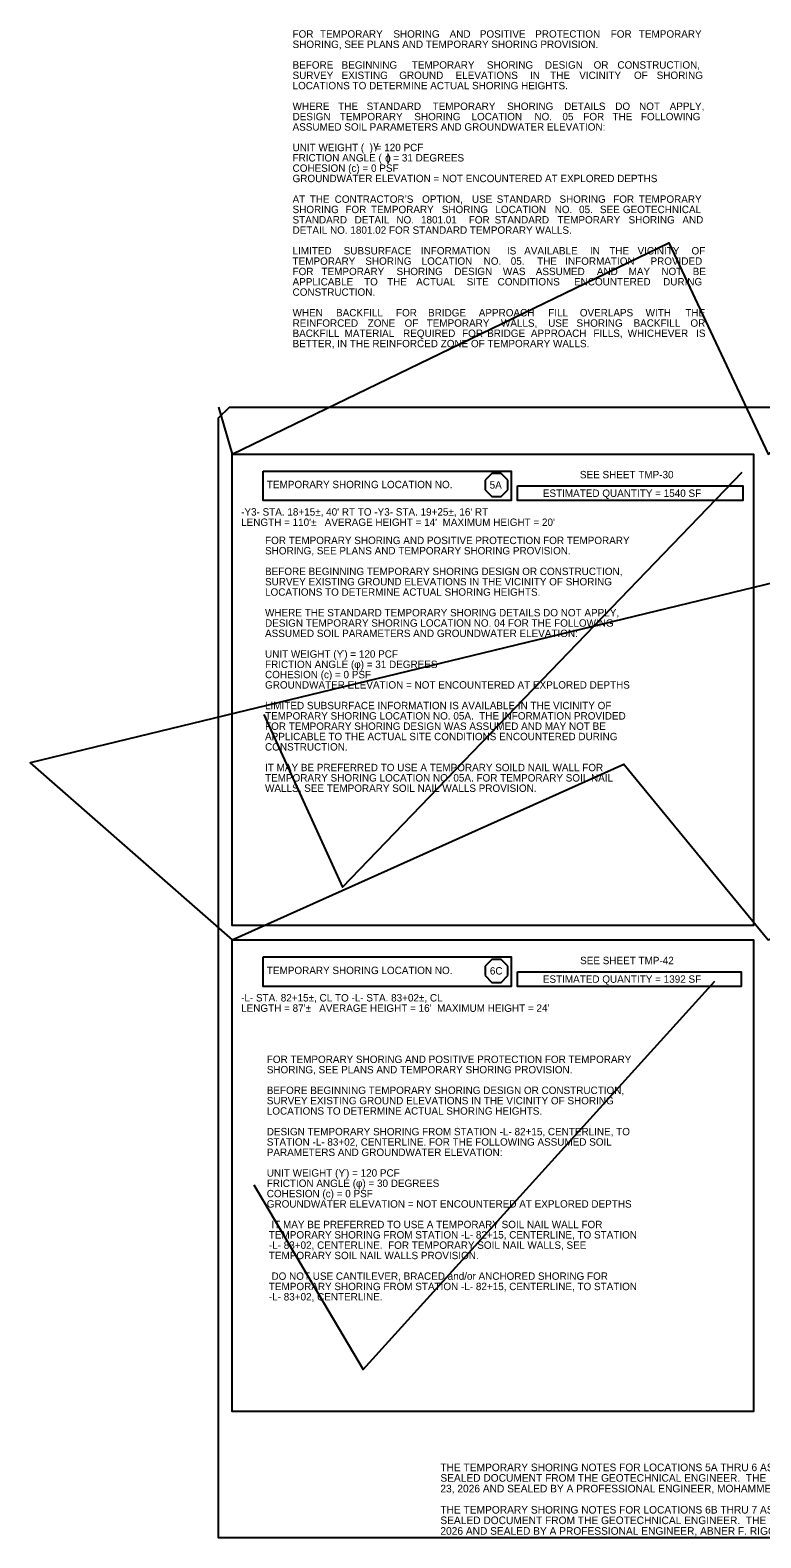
# Model space of a CAD drawing. Extents: x 2487012 to 2497594, y 369516 to 371986.
# Drawn here: x 2492395 to 2493067, y 370242 to 371629 of the extents above; entities that cross this region are included whole.
import ezdxf

# ---------------------------------------------------------------- set-up
doc = ezdxf.new("R2010")
doc.units = 0
for name, color, linetype in [('Scratch_Level_2', 7, 'Continuous'), ('Scratch_Level_3', 7, 'Continuous'), ('Scratch_Level_4', 7, 'Continuous'), ('Scratch_Level_6', 7, 'Continuous'), ('TC LABEL TEMP SHORING', 7, 'Continuous'), ('TC SHEET BORDER LINE THIN', 7, 'Continuous'), ('TC SHEET LAYOUT SHAPE', 7, 'Continuous'), ('TC SHEET TEXT', 7, 'Continuous')]:
    doc.layers.add(name, color=color, linetype=linetype)

msp = doc.modelspace()

# ---------------------------------------------------------------- linework, layer by layer
at = {"layer": 'Scratch_Level_2'}
msp.add_lwpolyline([(2492600.6, 370566.9), (2492701.1, 370397.1), (2493024.5, 370754.4)], dxfattribs=at)
at = {"layer": 'Scratch_Level_3'}
msp.add_line((2492568.3, 371282.3), (2492568.3, 371282.3), dxfattribs=at)
at = {"layer": 'Scratch_Level_4'}
msp.add_lwpolyline([(2492609.8, 370999.5), (2492682.2, 370840.9), (2493049.8, 371222.4)], dxfattribs=at)
at = {"layer": 'Scratch_Level_6'}
msp.add_lwpolyline([(2492568.3, 371282.3), (2492580.7, 371239.1), (2492982.2, 371433.4), (2493073.6, 371239.1), (2493388.3, 371445.4), (2493566.5, 371239.1), (2492395, 370955.2), (2492580.7, 370792.3), (2492940.9, 370953.9), (2493073.6, 370792.3), (2493429.6, 370924.6), (2493566.5, 370792.3)], dxfattribs=at)
at = {"layer": 'TC LABEL TEMP SHORING'}
for p, q in [((2492819.6, 371221.2), (2492813.5, 371215)), ((2492813.5, 371215), (2492813.5, 371206.3)), ((2492828.2, 371221.2), (2492819.6, 371221.2)), ((2492834.3, 371215), (2492828.2, 371221.2)), ((2492834.3, 371206.3), (2492834.3, 371215)), ((2492813.5, 371206.3), (2492819.6, 371200.1)), ((2492828.2, 371200.1), (2492834.3, 371206.3)), ((2492819.6, 371200.1), (2492828.2, 371200.1)), ((2492819.6, 370774.3), (2492813.5, 370768.1)), ((2492828.2, 370774.3), (2492819.6, 370774.3)), ((2492834.3, 370768.1), (2492828.2, 370774.3)), ((2492813.5, 370768.1), (2492813.5, 370759.4)), ((2492813.5, 370759.4), (2492819.6, 370753.2)), ((2492828.2, 370753.2), (2492834.3, 370759.4)), ((2492834.3, 370759.4), (2492834.3, 370768.1)), ((2492819.6, 370753.2), (2492828.2, 370753.2))]:
    msp.add_line(p, q, dxfattribs=at)
at = {"layer": 'TC SHEET BORDER LINE THIN'}
for points in [[(2492580.7, 371239.1), (2493060.1, 371239.1), (2493060.1, 370805.5), (2492580.7, 370805.5)], [(2492609.2, 371223.5), (2492837.2, 371223.5), (2492837.2, 371196.3), (2492609.2, 371196.3)], [(2492843, 371209.9), (2493050.4, 371209.9), (2493050.4, 371196.3), (2492843, 371196.3)], [(2492580.7, 370792.3), (2493060.1, 370792.3), (2493060.1, 370358.6), (2492580.7, 370358.6)], [(2492609.2, 370776.7), (2492837.2, 370776.7), (2492837.2, 370749.4), (2492609.2, 370749.4)], [(2492843, 370763), (2493048.7, 370763), (2493048.7, 370749.4), (2492843, 370749.4)]]:
    msp.add_lwpolyline(points, close=True, dxfattribs=at)
at = {"layer": 'TC SHEET LAYOUT SHAPE'}
msp.add_lwpolyline([(2492568.3, 370690.8), (2492568.3, 371000.2), (2492568.3, 371272.3), (2492578.3, 371282.3), (2493021.4, 371282.3), (2493492.3, 371282.3), (2493813.3, 371282.3), (2493813.3, 371202.3), (2493898.3, 371202.3), (2493898.3, 371250.3), (2494058.3, 371250.3), (2494058.3, 370915.3), (2494058.3, 370636.1), (2494058.3, 370384.8), (2493703.3, 370384.8), (2493703.3, 370242.3), (2493330.2, 370242.3), (2493160.7, 370242.3), (2492807.9, 370242.3), (2492568.3, 370242.3)], close=True, dxfattribs=at)

# ---------------------------------------------------------------- texts
at = {"layer": 'TC LABEL TEMP SHORING'}
for s, height, p in [('γ', 7.2, (2492710.6, 371519.6)), ('    ɸ', 7.2, (2492710.6, 371508)), ('5A', 6.81, (2492817.5, 371207.3)), ('6C', 6.81, (2492817.7, 370760.4))]:
    msp.add_text(s, height=height, dxfattribs=at).set_placement(p)
at = {"layer": 'TC SHEET BORDER LINE THIN'}
for s, height, p in [('SHORING, SEE PLANS AND TEMPORARY SHORING PROVISION.', 6.814, (2492636.3, 371612.6)), ('FOR ', 6.81, (2492636.3, 371622.1)), ('TEMPORARY ', 6.81, (2492661.5, 371622.1)), ('SHORING ', 6.81, (2492729, 371622.1)), ('AND ', 6.81, (2492780.7, 371622.1)), ('POSITIVE ', 6.81, (2492808.5, 371622.1)), ('PROTECTION ', 6.814, (2492859.4, 371622.1)), ('FOR ', 6.81, (2492928.8, 371622.1)), ('TEMPORARY ', 6.81, (2492954.7, 371622.1)), ('SURVEY ', 6.81, (2492636.3, 371584.1)), ('BEFORE ', 6.81, (2492636.3, 371593.6)), ('EXISTING ', 6.81, (2492681.4, 371584.1)), ('BEGINNING ', 6.81, (2492681.4, 371593.6)), ('GROUND ', 6.81, (2492734.4, 371584.1)), ('TEMPORARY ', 6.81, (2492745.9, 371593.6)), ('ELEVATIONS ', 6.814, (2492786.2, 371584.1)), ('SHORING ', 6.81, (2492815, 371593.6)), ('IN ', 6.81, (2492854.6, 371584.1)), ('DESIGN ', 6.81, (2492868.3, 371593.6)), ('THE ', 6.81, (2492873.2, 371584.1)), ('VICINITY ', 6.81, (2492899.9, 371584.1)), ('OR ', 6.81, (2492913.1, 371593.6)), ('CONSTRUCTION, ', 6.814, (2492935, 371593.6)), ('OF ', 6.81, (2492950.2, 371584.1)), ('SHORING ', 6.81, (2492971.1, 371584.1)), ('LOCATIONS TO DETERMINE ACTUAL SHORING HEIGHTS.', 6.814, (2492636.3, 371574.6)), ('WHERE ', 6.81, (2492636.3, 371555.6)), ('THE ', 6.81, (2492678.3, 371555.6)), ('STANDARD ', 6.81, (2492704.4, 371555.6)), ('TEMPORARY ', 6.81, (2492765.1, 371555.6)), ('SHORING ', 6.81, (2492833.5, 371555.6)), ('DETAILS ', 6.81, (2492886, 371555.6)), ('DO ', 6.81, (2492933, 371555.6)), ('NOT ', 6.81, (2492954.9, 371555.6)), ('APPLY, ', 6.81, (2492983, 371555.6)), ('DESIGN ', 6.81, (2492636.3, 371546.1)), ('TEMPORARY ', 6.81, (2492679.8, 371546.1)), ('SHORING ', 6.81, (2492748.2, 371546.1)), ('LOCATION ', 6.81, (2492800.8, 371546.1)), ('NO. ', 6.81, (2492858.7, 371546.1)), ('05 ', 6.81, (2492884.4, 371546.1)), ('FOR ', 6.81, (2492903.6, 371546.1)), ('THE ', 6.81, (2492930.5, 371546.1)), ('FOLLOWING ', 6.81, (2492956.6, 371546.1)), ('ASSUMED SOIL PARAMETERS AND GROUNDWATER ELEVATION:', 6.814, (2492636.3, 371536.6)), ('UNIT WEIGHT (  ) = 120 PCF', 6.814, (2492636.3, 371517.7)), ('FRICTION ANGLE (  ) = 31 DEGREES', 6.814, (2492636.3, 371508.2)), ('COHESION (c) = 0 PSF', 6.814, (2492636.3, 371498.7)), ('GROUNDWATER ELEVATION = NOT ENCOUNTERED AT EXPLORED DEPTHS', 6.814, (2492636.3, 371489.2)), ('AT ', 6.81, (2492636.3, 371470.2)), ('SHORING ', 6.81, (2492636.3, 371460.7)), ('THE ', 6.81, (2492652.1, 371470.2)), ('CONTRACTOR’S ', 6.814, (2492675, 371470.2)), ('FOR ', 6.81, (2492684.9, 371460.7)), ('TEMPORARY ', 6.81, (2492708.4, 371460.7)), ('OPTION, ', 6.81, (2492755.4, 371470.2)), ('SHORING ', 6.81, (2492773.5, 371460.7)), ('USE ', 6.81, (2492801.2, 371470.2)), ('LOCATION ', 6.81, (2492822.8, 371460.7)), ('STANDARD ', 6.81, (2492824, 371470.2)), ('NO. ', 6.81, (2492877.3, 371460.7)), ('SHORING ', 6.81, (2492881.7, 371470.2)), ('05. ', 6.81, (2492899.7, 371460.7)), ('SEE ', 6.81, (2492918.9, 371460.7)), ('FOR ', 6.81, (2492931.1, 371470.2)), ('GEOTECHNICAL ', 6.814, (2492940, 371460.7)), ('TEMPORARY ', 6.81, (2492954.7, 371470.2)), ('STANDARD ', 6.81, (2492636.3, 371451.2)), ('DETAIL ', 6.81, (2492693.4, 371451.2)), ('NO. ', 6.81, (2492731.8, 371451.2)), ('1801.01 ', 6.81, (2492754.4, 371451.2)), ('FOR ', 6.81, (2492798.3, 371451.2)), ('STANDARD ', 6.81, (2492822.1, 371451.2)), ('TEMPORARY ', 6.81, (2492879.9, 371451.2)), ('SHORING ', 6.81, (2492945.2, 371451.2)), ('AND ', 6.81, (2492994.7, 371451.2)), ('DETAIL NO. 1801.02 FOR STANDARD TEMPORARY WALLS.', 6.814, (2492636.3, 371441.7)), ('LIMITED ', 6.81, (2492636.3, 371422.7)), ('SUBSURFACE ', 6.814, (2492683.3, 371422.7)), ('INFORMATION ', 6.814, (2492754.3, 371422.7)), ('IS ', 6.81, (2492833.4, 371422.7)), ('AVAILABLE ', 6.81, (2492849.3, 371422.7)), ('IN ', 6.81, (2492909.7, 371422.7)), ('THE ', 6.81, (2492927.5, 371422.7)), ('VICINITY ', 6.81, (2492953.5, 371422.7)), ('OF ', 6.81, (2493003.1, 371422.7)), ('TEMPORARY ', 6.81, (2492636.3, 371413.2)), ('FOR ', 6.81, (2492636.3, 371403.7)), ('TEMPORARY ', 6.81, (2492662.9, 371403.7)), ('SHORING ', 6.81, (2492703.2, 371413.2)), ('SHORING ', 6.81, (2492731.9, 371403.7)), ('LOCATION ', 6.81, (2492755, 371413.2)), ('DESIGN ', 6.81, (2492785, 371403.7)), ('NO. ', 6.81, (2492812, 371413.2)), ('WAS ', 6.81, (2492829.7, 371403.7)), ('05. ', 6.81, (2492836.9, 371413.2)), ('ASSUMED ', 6.81, (2492859.9, 371403.7)), (' THE ', 6.81, (2492858.6, 371413.2)), ('INFORMATION ', 6.814, (2492887, 371413.2)), ('AND ', 6.81, (2492916.1, 371403.7)), ('MAY ', 6.81, (2492945.3, 371403.7)), ('PROVIDED ', 6.81, (2492965.4, 371413.2)), ('NOT ', 6.81, (2492975.4, 371403.7)), ('BE ', 6.81, (2493004.2, 371403.7)), ('APPLICABLE ', 6.814, (2492636.3, 371394.2)), ('TO ', 6.81, (2492702, 371394.2)), ('THE ', 6.81, (2492723.2, 371394.2)), ('ACTUAL ', 6.81, (2492750, 371394.2)), ('SITE ', 6.81, (2492796.4, 371394.2)), ('CONDITIONS ', 6.814, (2492824.8, 371394.2)), ('ENCOUNTERED ', 6.814, (2492895.1, 371394.2)), ('DURING ', 6.81, (2492977, 371394.2)), ('CONSTRUCTION.', 6.814, (2492636.3, 371384.7)), ('WHEN ', 6.81, (2492636.3, 371365.7)), ('BACKFILL ', 6.81, (2492676.3, 371365.7)), ('FOR ', 6.81, (2492731.4, 371365.7)), ('BRIDGE ', 6.81, (2492760.9, 371365.7)), ('APPROACH ', 6.81, (2492807.5, 371365.7)), ('FILL ', 6.81, (2492871.4, 371365.7)), ('OVERLAPS ', 6.81, (2492900.4, 371365.7)), ('WITH ', 6.81, (2492960.9, 371365.7)), ('THE ', 6.81, (2492997.4, 371365.7)), ('REINFORCED ', 6.814, (2492636.3, 371356.2)), ('BACKFILL ', 6.81, (2492636.3, 371346.8)), ('ZONE ', 6.81, (2492705.4, 371356.2)), ('REQUIRED ', 6.81, (2492737.9, 371346.8)), ('OF ', 6.81, (2492739.3, 371356.2)), ('TEMPORARY ', 6.81, (2492759.6, 371356.2)), ('FOR ', 6.81, (2492792.1, 371346.8)), ('BRIDGE ', 6.81, (2492815.2, 371346.8)), ('WALLS, ', 6.81, (2492827.9, 371356.2)), ('APPROACH ', 6.81, (2492855.4, 371346.8)), ('USE ', 6.81, (2492871.3, 371356.2)), ('SHORING ', 6.81, (2492897.3, 371356.2)), ('FILLS, ', 6.81, (2492912.9, 371346.8)), ('WHICHEVER ', 6.81, (2492944.4, 371346.8)), ('BACKFILL ', 6.81, (2492949.8, 371356.2)), ('OR ', 6.81, (2493002.1, 371356.2)), ('IS ', 6.81, (2493007.4, 371346.8)), ('BETTER, IN THE REINFORCED ZONE OF TEMPORARY WALLS.', 6.814, (2492636.3, 371337.3)), ('MATERIAL ', 6.81, (2492684.2, 371346.8)), ('FOR TEMPORARY SHORING AND POSITIVE PROTECTION FOR TEMPORARY ', 6.814, (2492611, 371156.3)), ('SHORING, SEE PLANS AND TEMPORARY SHORING PROVISION.', 6.814, (2492611, 371146.8)), ('BEFORE BEGINNING TEMPORARY SHORING DESIGN OR CONSTRUCTION, ', 6.814, (2492611, 371127.8)), ('SURVEY EXISTING GROUND ELEVATIONS IN THE VICINITY OF SHORING ', 6.814, (2492611, 371118.3)), ('LOCATIONS TO DETERMINE ACTUAL SHORING HEIGHTS.', 6.814, (2492611, 371108.8)), ('WHERE THE STANDARD TEMPORARY SHORING DETAILS DO NOT APPLY, ', 6.814, (2492611, 371089.8)), ('ASSUMED SOIL PARAMETERS AND GROUNDWATER ELEVATION:', 6.814, (2492611, 371070.8)), ('DESIGN TEMPORARY SHORING LOCATION NO. 04 FOR THE FOLLOWING ', 6.814, (2492611, 371080.3)), ('UNIT WEIGHT (ϒ) = 120 PCF ', 6.814, (2492611, 371051.8)), ('FRICTION ANGLE (φ) = 31 DEGREES ', 6.814, (2492611, 371042.3)), ('COHESION (c) = 0 PSF ', 6.814, (2492611, 371032.9)), ('GROUNDWATER ELEVATION = NOT ENCOUNTERED AT EXPLORED DEPTHS', 6.814, (2492611, 371023.4)), ('LIMITED SUBSURFACE INFORMATION IS AVAILABLE IN THE VICINITY OF ', 6.814, (2492611, 371004.4)), ('TEMPORARY SHORING LOCATION NO. 05A.  THE INFORMATION PROVIDED ', 6.814, (2492611, 370994.9)), ('APPLICABLE TO THE ACTUAL SITE CONDITIONS ENCOUNTERED DURING ', 6.814, (2492611, 370975.9)), ('FOR TEMPORARY SHORING DESIGN WAS ASSUMED AND MAY NOT BE ', 6.814, (2492611, 370985.4)), ('CONSTRUCTION.', 6.814, (2492611, 370966.4)), ('IT MAY BE PREFERRED TO USE A TEMPORARY SOILD NAIL WALL FOR ', 6.814, (2492611, 370947.4)), ('TEMPORARY SHORING LOCATION NO. 05A. FOR TEMPORARY SOIL NAIL ', 6.814, (2492611, 370937.9)), ('WALLS, SEE TEMPORARY SOIL NAIL WALLS PROVISION.', 6.814, (2492611, 370928.4)), ('SHORING, SEE PLANS AND TEMPORARY SHORING PROVISION.', 6.814, (2492612.6, 370669.5)), ('FOR TEMPORARY SHORING AND POSITIVE PROTECTION FOR TEMPORARY ', 6.814, (2492612.6, 370679)), ('SURVEY EXISTING GROUND ELEVATIONS IN THE VICINITY OF SHORING ', 6.814, (2492612.6, 370641)), ('BEFORE BEGINNING TEMPORARY SHORING DESIGN OR CONSTRUCTION, ', 6.814, (2492612.6, 370650.5)), ('LOCATIONS TO DETERMINE ACTUAL SHORING HEIGHTS.', 6.814, (2492612.6, 370631.5)), ('DESIGN TEMPORARY SHORING FROM STATION -L- 82+15, CENTERLINE, TO ', 6.814, (2492612.6, 370612.5)), ('STATION -L- 83+02, CENTERLINE. FOR THE FOLLOWING ASSUMED SOIL ', 6.814, (2492612.6, 370603)), ('PARAMETERS AND GROUNDWATER ELEVATION:', 6.814, (2492612.6, 370593.5)), ('UNIT WEIGHT (ϒ) = 120 PCF', 6.814, (2492612.6, 370574.5)), ('FRICTION ANGLE (φ) = 30 DEGREES', 6.814, (2492612.6, 370565)), ('COHESION (c) = 0 PSF', 6.814, (2492612.6, 370555.5)), ('GROUNDWATER ELEVATION = NOT ENCOUNTERED AT EXPLORED DEPTHS', 6.814, (2492612.6, 370546)), ('TEMPORARY SHORING FROM STATION -L- 82+15, CENTERLINE, TO STATION ', 6.814, (2492614.5, 370517.6)), ('IT MAY BE PREFERRED TO USE A TEMPORARY SOIL NAIL WALL FOR ', 6.814, (2492616.9, 370527.1)), ('-L- 83+02, CENTERLINE.  FOR TEMPORARY SOIL NAIL WALLS, SEE ', 6.814, (2492614.5, 370508.1)), ('TEMPORARY SOIL NAIL WALLS PROVISION.', 6.814, (2492614.5, 370498.6)), ('DO NOT USE CANTILEVER, BRACED and/or ANCHORED SHORING FOR ', 6.814, (2492616.9, 370479.6)), ('TEMPORARY SHORING FROM STATION -L- 82+15, CENTERLINE, TO STATION ', 6.814, (2492614.5, 370470.1)), ('-L- 83+02, CENTERLINE.', 6.814, (2492614.5, 370460.6))]:
    msp.add_text(s, height=height, dxfattribs=at).set_placement(p)
at = {"layer": 'TC SHEET TEXT'}
for s, height, p in [('SEE SHEET TMP-30', 6.814, (2492900.5, 371216.8)), ('TEMPORARY SHORING LOCATION NO.', 6.814, (2492612.7, 371207.7)), ('ESTIMATED QUANTITY = 1540 SF', 6.814, (2492866.4, 371199.7)), ("-Y3- STA. 18+15±, 40' RT TO -Y3- STA. 19+25±, 16' RT", 6.814, (2492589, 371182.5)), ("LENGTH = 110'±   AVERAGE HEIGHT = 14'  MAXIMUM HEIGHT = 20'", 6.814, (2492589, 371173)), ('SEE SHEET TMP-42', 6.814, (2492900.7, 370769.9)), ('TEMPORARY SHORING LOCATION NO.', 6.814, (2492612.7, 370760.8)), ('ESTIMATED QUANTITY = 1392 SF', 6.814, (2492866.4, 370752.8)), ('-L- STA. 82+15±, CL TO -L- STA. 83+02±, CL', 6.814, (2492589, 370735.6)), ("LENGTH = 87'±   AVERAGE HEIGHT = 16'  MAXIMUM HEIGHT = 24'", 6.814, (2492589, 370726.1)), ('THE TEMPORARY SHORING NOTES FOR LOCATIONS 5A THRU 6 AS SHOWN ON THIS SHEET WERE PROVIDED THROUGH A ', 7, (2492772.2, 370303.6)), ('SEALED DOCUMENT FROM THE GEOTECHNICAL ENGINEER.  THE DOCUMENT WAS SUBMITTED IN A MEMO DATED APRIL ', 7, (2492772.2, 370293.9)), ('23, 2026 AND SEALED BY A PROFESSIONAL ENGINEER, MOHAMMED A. MULLA, PE, LICENSE #18979.', 7, (2492772.2, 370284.1)), ('THE TEMPORARY SHORING NOTES FOR LOCATIONS 6B THRU 7 AS SHOWN ON THIS SHEET WERE PROVIDED THROUGH A ', 7, (2492772.2, 370264.6)), ('SEALED DOCUMENT FROM THE GEOTECHNICAL ENGINEER.  THE DOCUMENT WAS SUBMITTED IN A MEMO DATED MAY 6, ', 7, (2492772.2, 370254.9)), ('2026 AND SEALED BY A PROFESSIONAL ENGINEER, ABNER F. RIGGS, PE, LICENSE #14155.', 7, (2492772.2, 370245.1))]:
    msp.add_text(s, height=height, dxfattribs=at).set_placement(p)

doc.saveas('drawing.dxf')
